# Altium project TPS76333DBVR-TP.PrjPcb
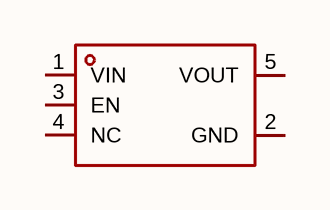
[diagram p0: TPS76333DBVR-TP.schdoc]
1 sheet, 1 parts. Net scope: global (net labels, ports and power ports of the same name join across sheets).

## Sheet TPS76333DBVR-TP.schdoc
size 127 x 101 mm

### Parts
U?  tps76333dbvr-tp  [SOT-23-5_L3.0-W1.6-P0.95-LS2.8-BR]  (value not drawn)

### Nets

Not connected (* = marked no-connect by the designer): U? 1(VIN) 2(GND) 3(EN) 4(NC) 5(VOUT)

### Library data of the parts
U? = tps76333dbvr-tp: 输出极性:正极;工作电压:12V;输出电压:3.3V;输出电流:150mA;电源纹波抑制比(PSRR):70dB@(1kHz);输出类型:固定;; Manufacturer: TECH PUBLIC(台舟); AddInBom: yes; ModelId: 72410e292833493f86746b22636ce101; ModelTransform: 110.236,116.1415,0,0,0,0,0.002,0.001,0; Output Configuration: 正极; Voltage - Supply: 12V; Output Voltage: 3.3V; Output Current: 150mA; Voltage Dropout: 420mV@(100mA); standby current: 2uA; Output Type: 固定; Number of Outputs: 1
